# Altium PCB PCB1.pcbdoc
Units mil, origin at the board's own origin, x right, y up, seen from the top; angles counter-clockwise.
Board outline 1614.07 x 3024.69 mil, 2 copper layers (Top Layer, Bottom Layer); 22 components, 14 nets, 88 pads, 0 vias.
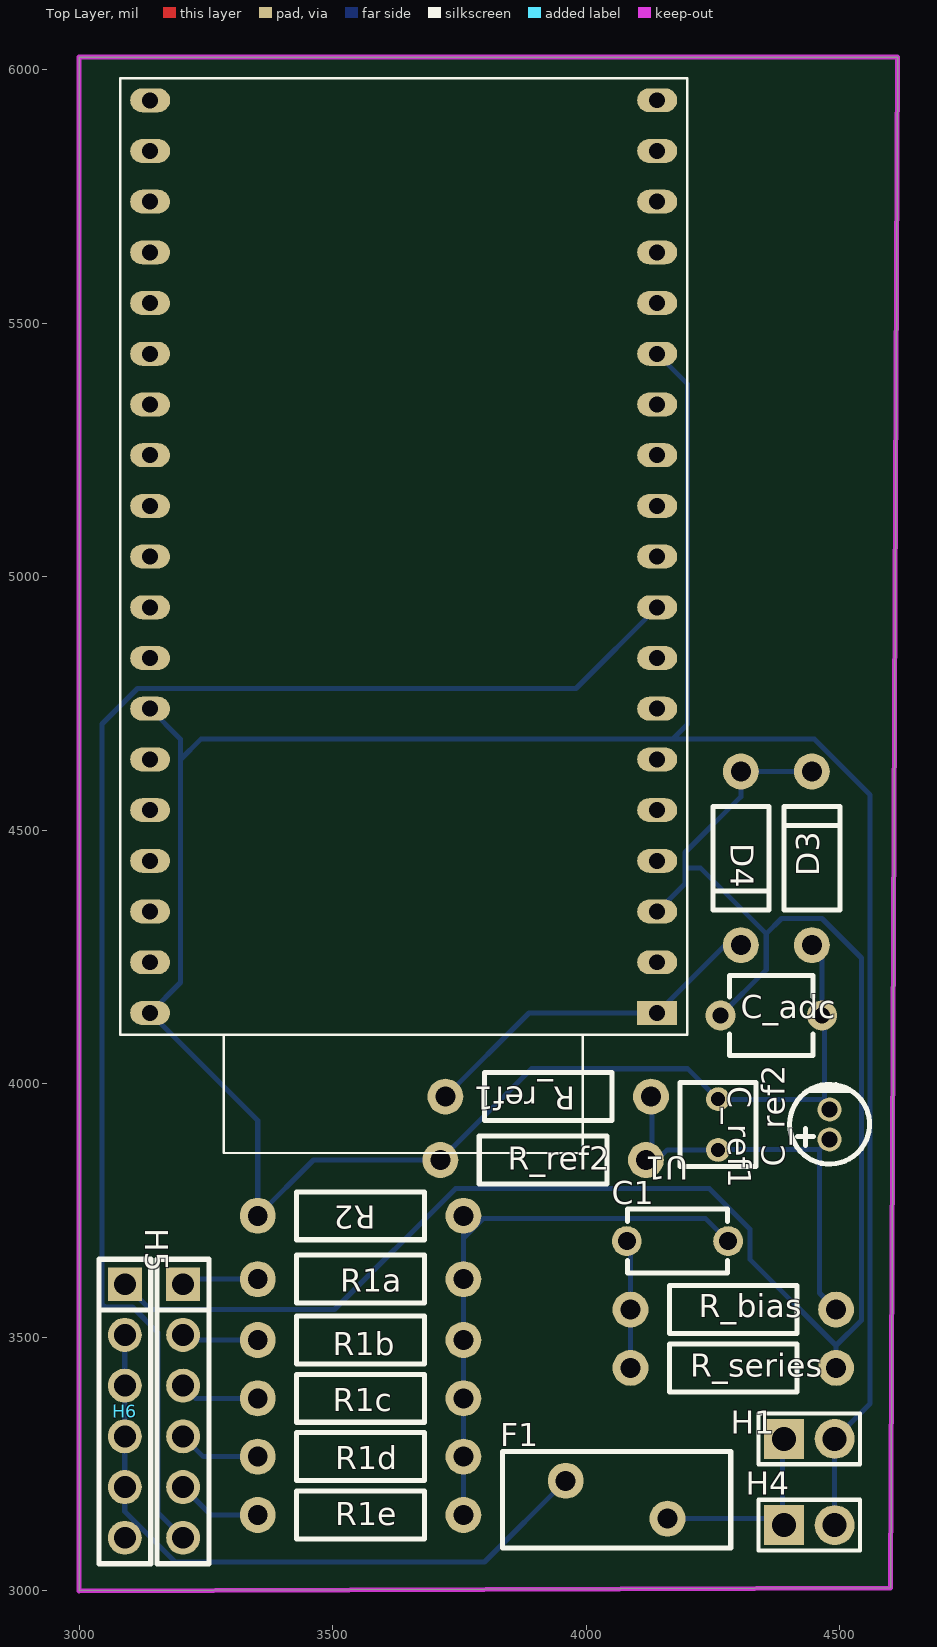
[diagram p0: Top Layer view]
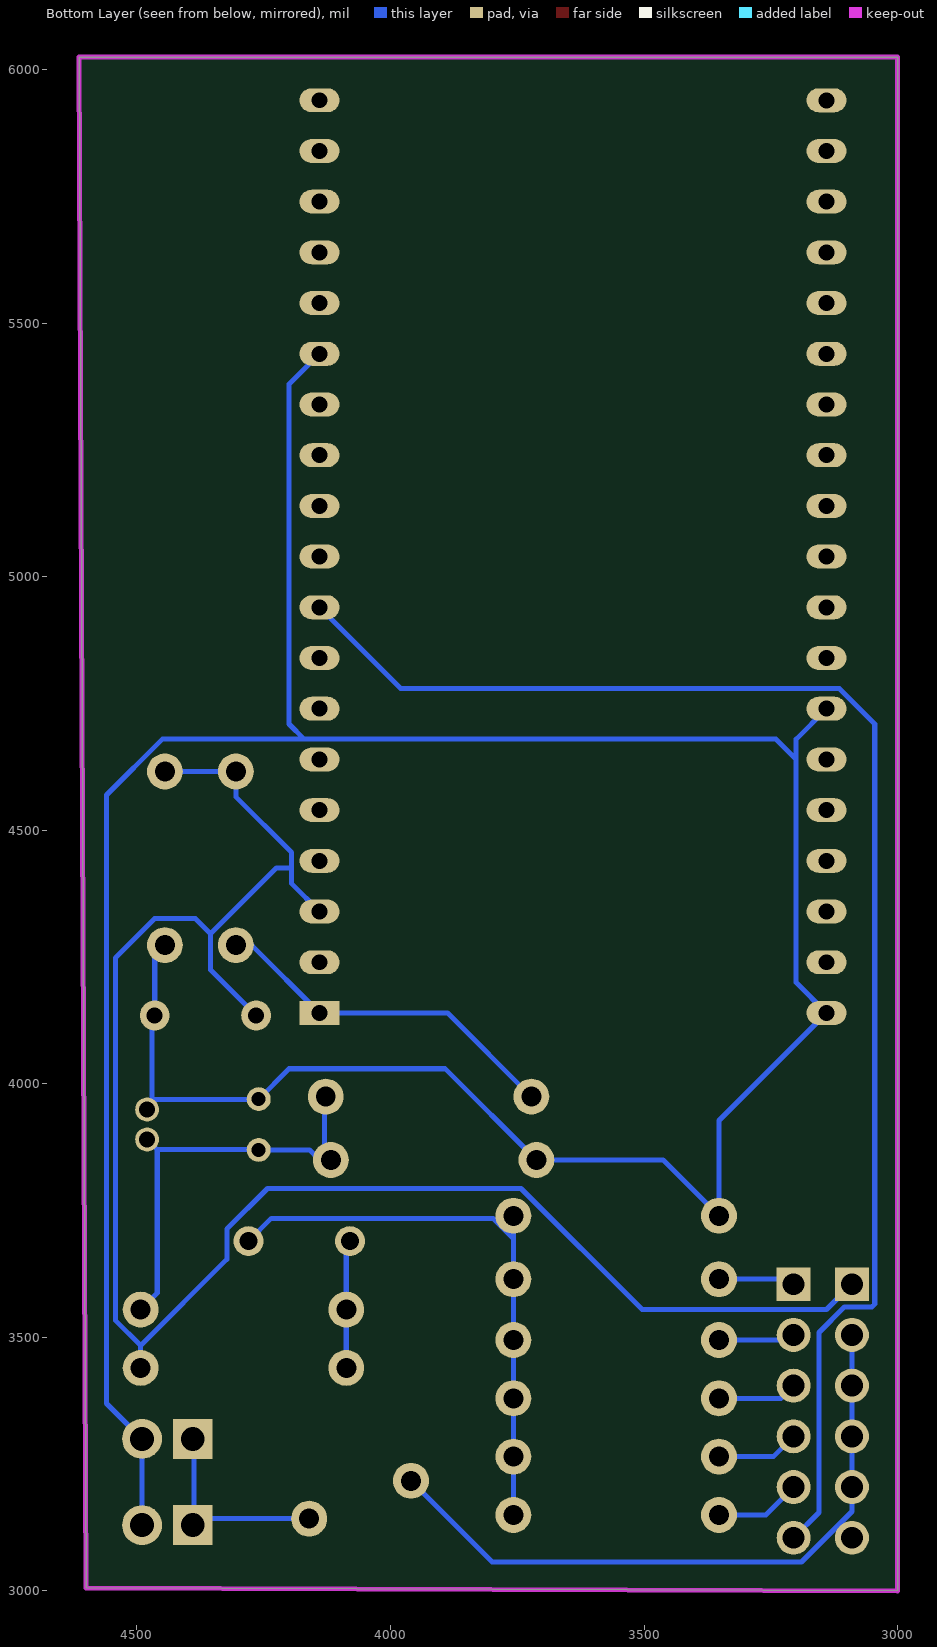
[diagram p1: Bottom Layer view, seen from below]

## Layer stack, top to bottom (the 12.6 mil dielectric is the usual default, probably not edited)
Top Layer: signal copper (thickness not stored)
Dielectric: dielectric 12.6, FR-4, Dk 4.8
Bottom Layer: signal copper (thickness not stored)

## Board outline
3000,3000 3000,6024.69 4614.07,6024.69 4600.4,3005.97

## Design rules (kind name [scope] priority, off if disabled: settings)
BoardOutlineClearance copperThickness1oz [All] p0: genericclearance=10 ignorepadtopadclearanceinfootprint=FALSE except(0: Arc-SplitContinuation Track-SplitContinuation SMDPad-SplitContinuation THPad-SplitContinuation Via-SplitContinuation Fill-SplitContinuation Poly-SplitContinuation Region-SplitContinuation Text-SplitContinuation; 6: Track-CutoutEdge SMDPad-CutoutEdge THPad-CutoutEdge Via-CutoutEdge Region-CutoutEdge; 11.8: Track-OutlineEdge SMDPad-OutlineEdge THPad-OutlineEdge Via-OutlineEdge Fill-OutlineEdge Region-OutlineEdge Poly-OutlineEdge Text-OutlineEdge Fill-CutoutEdge)
BoardOutlineClearance copperThickness2oz [All] p0: genericclearance=10 ignorepadtopadclearanceinfootprint=FALSE except(0: Arc-SplitContinuation Track-SplitContinuation SMDPad-SplitContinuation THPad-SplitContinuation Via-SplitContinuation Fill-SplitContinuation Poly-SplitContinuation Region-SplitContinuation Text-SplitContinuation; 6: Track-CutoutEdge SMDPad-CutoutEdge THPad-CutoutEdge Via-CutoutEdge Region-CutoutEdge; 11.8: Track-OutlineEdge SMDPad-OutlineEdge THPad-OutlineEdge Via-OutlineEdge Fill-OutlineEdge Region-OutlineEdge Poly-OutlineEdge Text-OutlineEdge Fill-CutoutEdge)
Clearance copperThickness1oz [(InNet('$1N1104') OR InNet('$1N1273') OR InNet('$1N188') OR InNet('$1N365') OR InNet('$1N393') OR InNet('$1N1047') OR InNet('$1N1061') OR InNet('$1N2260') OR InNet('$1N2251') OR InNet('$1N2256') OR InNet('$1N2825') OR InNet('$1N3077') OR InNet('$1N3138') OR InNet('$1N3405'))] p1: gap=7 ignorepadtopadclearanceinfootprint=FALSE except(4: Track-Track; 6: Track-SMDPad SMDPad-SMDPad Track-THPad SMDPad-THPad THPad-THPad Track-Via SMDPad-Via THPad-Via Via-Via SMDPad-Fill THPad-Fill Via-Fill Fill-Fill Track-Region SMDPad-Region THPad-Region Via-Region Region-Region Track-Poly SMDPad-Poly THPad-Poly Via-Poly Fill-Poly Region-Poly Poly-Poly Track-Text SMDPad-Text THPad-Text Via-Text Fill-Text Region-Text Poly-Text Text-Text; 6.9: Track-Hole SMDPad-Hole THPad-Hole Via-Hole Fill-Hole Region-Hole Poly-Hole Text-Hole Sheet-Hole; 11.8: Track-Fill Fill-Region Track-Sheet SMDPad-Sheet THPad-Sheet Via-Sheet Fill-Sheet Region-Sheet Poly-Sheet Text-Sheet)
Clearance copperThickness2oz [All] p1: gap=7 ignorepadtopadclearanceinfootprint=FALSE except(6: Track-SMDPad SMDPad-SMDPad Track-THPad SMDPad-THPad THPad-THPad Track-Via SMDPad-Via THPad-Via Via-Via SMDPad-Fill THPad-Fill Via-Fill Fill-Fill Track-Region SMDPad-Region THPad-Region Via-Region Region-Region Track-Poly SMDPad-Poly THPad-Poly Via-Poly Fill-Poly Region-Poly Poly-Poly Track-Text SMDPad-Text THPad-Text Via-Text Fill-Text Region-Text Poly-Text Text-Text; 6.9: Track-Hole SMDPad-Hole THPad-Hole Via-Hole Fill-Hole Region-Hole Poly-Hole Text-Hole Sheet-Hole; 8: Track-Track; 11.8: Track-Fill Fill-Region Track-Sheet SMDPad-Sheet THPad-Sheet Via-Sheet Fill-Sheet Region-Sheet Poly-Sheet Text-Sheet)
DiffPairsRouting differentialPair [All] p1: maxuncoupledlength=10 minlimit=6 maxlimit=6 mostfreqgap=6 toplayer_minwidth=5 toplayer_prefwidth=10 toplayer_maxwidth=100 bottomlayer_minwidth=5 bottomlayer_prefwidth=10 bottomlayer_maxwidth=100
PasteMaskExpansion pasteMaskExpansion [All] p1: expansion=0
PlaneConnect innerPlane [All] p1: planeconnectstyle=Relief reliefexpansion=20 reliefentries=4 reliefconductorwidth=10 reliefairgap=10
PolygonConnect copperRegion [All] p1: connectstyle=Relief reliefentries=4 reliefconductorwidth=10 polygonreliefangle="90 Angle" airgapwidth=10
RoutingVias viaSize [All] p1: viastyle="Through Hole" holewidth=12.0078 minholewidth=11.811 maxholewidth=248.0314 width=24.0158 minwidth=19.685 maxwidth=393.7008
SolderMaskExpansion solderMaskExpansion [All] p1: useseparateexpansions=TRUE expansion=2 expansionbottom=2
Width copperThickness1oz [All] p1: maxlimit=100 minlimit=5 preferedwidth=10
Width copperThickness2oz [All] p1: maxlimit=100 minlimit=8 preferedwidth=10

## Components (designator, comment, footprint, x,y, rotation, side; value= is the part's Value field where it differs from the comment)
C1 "CD1H105MC9BEF4E100" CAP-TH_L5.0-W3.2-P5.08-D0.6 4180,3689.69 r0 top
C_adc "CD1H103KC94ER1D000" CAP-TH_L4.2-W3.8-P5.08-D0.6 4365,4134.69 r0 top
C_ref1 "178MU0011" CAP-TH_L4.2-W3.8-P2.54-D0.5 4260,3919.69 r270 top
C_ref2 "KF106M025C05RR0VH2FP0" CAP-TH_BD4.0-P1.50-D0.8-FD 4480,3919.69 r90 top
D3 "1N5819_C2474" DO-41_BD2.4-L4.7-P8.70-D0.9-FD 4445,4444.69 r90 top
D4 "1N5819_C2474" DO-41_BD2.4-L4.7-P8.70-D0.9-FD 4305,4444.69 r270 top
F1 "FRV075-240F" FUSE-TH_L11.5-W4.8-P5.10-S1.9 4060,3179.69 r0 top
H1 "HX PH254-01-02-Z-L11.5 male header connector" HDR-TH_2P-P2.54-V-M 4440,3299.69 r0 top
H4 "HX PH254-01-02-Z-L11.5 male header connector" HDR-TH_2P-P2.54-V-M 4440,3129.69 r0 top
H5 "HX PH254-01-06-Z-L11.5 through hole header" HDR-TH_6P-P2.54-V-M 3205,3354.69 r270 top
H6 "HX PH254-01-06-Z-L11.5 through hole header" HDR-TH_6P-P2.54-V-M 3090,3354.69 r270 top
R1a "LR1F10K" RES-TH_BD2.3-L6.3-P10.30-D0.6 3555,3614.69 r0 top
R1b "LR1F10K" RES-TH_BD2.3-L6.3-P10.30-D0.6 3555,3494.69 r0 top
R1c "LR1F10K" RES-TH_BD2.3-L6.3-P10.30-D0.6 3555,3379.69 r0 top
R1d "LR1F10K" RES-TH_BD2.3-L6.3-P10.30-D0.6 3555,3264.69 r0 top
R1e "LR1F10K" RES-TH_BD2.3-L6.3-P10.30-D0.6 3555,3149.69 r0 top
R2 "LR1F10K" RES-TH_BD2.3-L6.3-P10.30-D0.6 3555,3739.69 r180 top
R_bias "LR1F10K" RES-TH_BD2.3-L6.3-P10.30-D0.6 4290,3554.69 r0 top
R_ref1 "LR1F10K" RES-TH_BD2.3-L6.3-P10.30-D0.6 3925,3974.69 r180 top
R_ref2 "LR1F10K" RES-TH_BD2.3-L6.3-P10.30-D0.6 3915,3849.69 r0 top
R_series "LR1F10K" RES-TH_BD2.3-L6.3-P10.30-D0.6 4290,3439.69 r0 top
U1 "ESP32-DevKitC" ESP32-DevKitC 4140,4139.69 r180 top

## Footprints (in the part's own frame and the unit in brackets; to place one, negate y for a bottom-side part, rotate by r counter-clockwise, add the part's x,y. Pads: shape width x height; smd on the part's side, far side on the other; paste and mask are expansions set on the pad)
CAP-TH_BD4.0-P1.50-D0.8-FD [mm]
  round 1.2 hole 0.8: 1(-0.75,0) 2(0.75,0)
  silkscreen extent -1.98,-2 2.06,2
CAP-TH_L4.2-W3.8-P2.54-D0.5 [mm]
  round 1.2 hole 0.7: 1(-1.27,0) 2(1.27,0)
  silkscreen extent -2.1,-1.9 2.1,1.9
CAP-TH_L4.2-W3.8-P5.08-D0.6 [mm]
  round 1.5 hole 0.8: 1(-2.54,0) 2(2.54,0)
  silkscreen extent -2.1,-2 2.1,2
CAP-TH_L5.0-W3.2-P5.08-D0.6 [mm]
  round 1.5 hole 0.9: 1(-2.54,0) 2(2.54,0)
  silkscreen extent -2.5,-1.6 2.5,1.6
DO-41_BD2.4-L4.7-P8.70-D0.9-FD [mm]
  round 1.8 hole 1: 1(-4.35,0) 2(4.35,0)
  silkscreen extent -2.6,-1.4 2.6,1.4
ESP32-DevKitC [mm]
  rect 2x1.2 hole 0.8: 1(0,0)
  oval 2x1.2 hole 0.8: 2(0,-2.54) 3(0,-5.08) 4(0,-7.62) 5(0,-10.16) 6(0,-12.7) 7(0,-15.24) 8(0,-17.78) 9(0,-20.32) 10(0,-22.86) 11(0,-25.4) 12(0,-27.94) 13(0,-30.48) 14(0,-33.02) 15(0,-35.56) 16(0,-38.1) 17(0,-40.64) 18(0,-43.18) 19(0,-45.72) 20(25.396,-45.717) 21(25.396,-43.177) 22(25.4,-40.64) 23(25.4,-38.1) 24(25.4,-35.56) 25(25.4,-33.02) 26(25.4,-30.48) 27(25.4,-27.94) 28(25.4,-25.4) 29(25.4,-22.86) 30(25.4,-20.32) 31(25.4,-17.78) 32(25.4,-15.24) 33(25.4,-12.7) 34(25.4,-10.16) 35(25.4,-7.62) 36(25.4,-5.08) 37(25.4,-2.54) 38(25.4,0)
  silkscreen extent -1.5,-46.82 26.9,7.01
FUSE-TH_L11.5-W4.8-P5.10-S1.9 [mm]
  round 1.8 hole 1: 1(-2.55,0.95) 2(2.55,-0.95)
  silkscreen extent -5.72,-2.41 5.71,2.41
HDR-TH_2P-P2.54-V-M [mm]
  rect 2x2 hole 1.2: 1(-1.27,0)
  round 2 hole 1.2: 2(1.27,0)
  silkscreen extent -2.54,-1.27 2.54,1.27
HDR-TH_6P-P2.54-V-M [mm]
  rect 1.7x1.7 hole 1.1: 1(-6.35,0)
  round 1.7 hole 1.1: 2(-3.81,0) 3(-1.27,0) 4(1.27,0) 5(3.81,0) 6(6.35,0)
  silkscreen extent -7.6,-1.3 7.65,1.3
RES-TH_BD2.3-L6.3-P10.30-D0.6 [mm]
  round 1.8 hole 1: 1(-5.15,0) 2(5.15,0)
  silkscreen extent -3.2,-1.2 3.2,1.2

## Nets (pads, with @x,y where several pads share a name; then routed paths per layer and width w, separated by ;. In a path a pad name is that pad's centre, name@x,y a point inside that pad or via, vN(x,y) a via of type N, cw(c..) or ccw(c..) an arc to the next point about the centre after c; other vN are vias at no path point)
$1N188: C_adc.2 C_ref1.1 C_ref2.2 D3.1 H1.2 H4.2 R2.2 R_ref2.1 U1.14 U1.32 U1.38 | length 6427.7
  Bottom Layer w10: U1.32 3200,4679.69 3200,4639.69 ; U1.14 4200,5379.69 4200,4709.69 4170,4679.69 ; D3.1 4465,4253.43 C_adc.2 4470,4129.69 C_ref2.2@4470,3969.22 ; C_ref2.2 4470,3959.22 C_ref2.2@4470,3969.22 ; H4.2 H1.2 4560,3369.69 4560,4569.69 4450,4679.69 4170,4679.69 ; 3200,4639.69 3240,4679.69 4170,4679.69 ; 3200,4639.69 3200,4199.69 U1.38 3352.24,3927.45 R2.2 3462.24,3849.69 R_ref2.1 3892.24,4029.69 4200,4029.69 C_ref1.1 4260.47,3969.22 C_ref2.2@4470,3969.22
$1N365: C_ref1.2 C_ref2.1 R_bias.2 R_ref1.1 R_ref2.2 | length 834
  Bottom Layer w10: R_ref2.2 R_ref2.2@4130,3849.69 ; R_ref1.1 4130,3972.45 R_ref2.2@4130,3849.69 ; C_ref2.1 4460,3870.16 ; R_bias.2 4460,3587.45 4460,3870.16 ; R_ref2.2@4130,3849.69 4140,3849.69 4160,3869.69 C_ref1.2 4260.47,3870.16 4460,3870.16
$1N393: D4.2 R_ref1.2 U1.1 | length 706.5
  Bottom Layer w10: R_ref1.2 3887.24,4139.69 U1.1 4273.74,4273.43 D4.2
$1N1047: H5.1 R1a.1 | length 151.4
  Bottom Layer w10: H5.1 3215,3614.69 R1a.1
$1N1061: H5.3 R1c.1 | length 157.6
  Bottom Layer w10: H5.3 3230,3379.69 R1c.1
$1N1104: C1.2 R1a.2 R1b.2 R1c.2 R1d.2 R1e.2 R2.1 | length 1147.5
  Bottom Layer w10: R1e.2 R1d.2 R1c.2 R1b.2 R1a.2 3757.76,3694.69 ; R2.1 3757.76,3694.69 ; C1.2 4235,3734.69 3797.76,3734.69 3757.76,3694.69
$1N1273: C1.1 R_bias.1 R_series.1 | length 253
  Bottom Layer w10: C1.1 4087.24,3682.45 R_bias.1 R_series.1
$1N2251: H5.4 R1d.1 | length 163.8
  Bottom Layer w10: H5.4 3245,3264.69 R1d.1
$1N2256: H5.5 R1e.1 | length 170
  Bottom Layer w10: H5.5 3260,3149.69 R1e.1
$1N2260: H5.2 R1b.1 | length 151.4
  Bottom Layer w10: H5.2 3215,3494.69 R1b.1
$1N2825: F1.2 H1.1 H4.1 | length 403.3
  Bottom Layer w10: F1.2 4360.4,3142.29 4370.4,3132.29 H4.1@4387.4,3132.29 ; H4.1 H4.1@4387.4,3132.29 ; H1.1 4387.4,3297.09 H4.1@4387.4,3132.29
$1N3077: F1.1 H6.2 H6.3 H6.4 H6.5 H6.6 | length 1364
  Bottom Layer w10: H6.6 3112.4,3127.09 3119.61,3127.09 ; H6.2 H6.3 H6.4 H6.5 3090,3156.7 3119.61,3127.09 ; F1.1 3799.61,3057.09 3189.61,3057.09 3119.61,3127.09
$1N3138: H5.6 U1.9 | length 2893.3
  Bottom Layer w10: H5.6 3155,3154.69 3155,3509.69 3105,3559.69 3050.77,3559.69 3045,3565.46 3045,4709.69 3115,4779.69 3980,4779.69 U1.9
$1N3405: C_adc.1 D3.2 D4.1 H6.1 R_series.2 U1.3 | length 3644.6
  Bottom Layer w10: H6.1 3140,3554.69 3503.74,3554.69 3742.76,3793.71 4242.76,3793.71 4322.76,3713.71 4322.76,3653.71 4492.76,3483.71 ; U1.3 4195,4394.69 4195,4425.95 ; C_adc.1 4355,4224.69 4355,4295.95 ; D3.2 D4.1 4305,4565.95 4195,4455.95 4195,4425.95 ; R_series.2 4492.76,3483.71 ; 4195,4425.95 4225,4425.95 4355,4295.95 ; 4355,4295.95 4385,4325.95 4465,4325.95 4542.76,4248.2 4542.76,3533.71 4492.76,3483.71
pads on no net: U1.2 U1.4 U1.5 U1.6 U1.7 U1.8 U1.10 U1.11 U1.12 U1.13 U1.15 U1.16 U1.17 U1.18 U1.19 U1.20 U1.21 U1.22 U1.23 U1.24 U1.25 U1.26 U1.27 U1.28 U1.29 U1.30 U1.31 U1.33 U1.34 U1.35 U1.36 U1.37

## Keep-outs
Board Outline Layer:
  the board outline again, w10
